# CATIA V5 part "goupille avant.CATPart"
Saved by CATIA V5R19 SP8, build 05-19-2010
Part number: goupille avant
Bounding box of the stored display mesh (mm): x -1.498 to 1.498, y 0 to 29, z -1.498 to 1.498
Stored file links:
  C:\Users\Arthur\Desktop\Catia parts\GLOCK\Poignée\goupille avant.CATPart
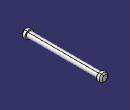
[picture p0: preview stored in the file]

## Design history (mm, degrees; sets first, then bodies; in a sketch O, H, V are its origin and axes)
Body1 (main body)
  Sketch1 on yz-plane, origin (0, 0, 0), H (0, 1, 0), V (0, 0, 1)
    line L1 (0, 0) -> (29, 0)
    line L2 (29, 0) -> (29, 1.5)
    line L3 (0, 1.5) -> (0, 0)
    line L4 (29, 1.5) -> (27.5, 1.5)
    line L5 (27.5, 1.5) -> (27.5, 1)
    line L6 (27.5, 1) -> (1.5, 1)
    line L7 (1.5, 1) -> (1.5, 1.5)
    point P7 (1.5, 1.5)
    line L8 (1.5, 1.5) -> (0, 1.5)
    distance L2 L3 = 29
    length L4 = 1.5
    length L8 = 1.5
    distance L6 L8 = 0.5
    distance L4 L1 = 1.5
    horizontal: L1 H, L4 H, L6 H, L8 H
    vertical: L2 V, L3 V, L5 V, L7 V
    coincidence: P7 L4
  Shaft1: profile Sketch1, axis Sketch1.L1, angle 360
  Chamfer1: length 0.5, angle 45, on edge [face of Shaft1 from Sketch1.L4 | face of Shaft1 from Sketch1.L2]; edge [face of Shaft1 from Sketch1.L3 | face of Shaft1 from Sketch1.L8]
